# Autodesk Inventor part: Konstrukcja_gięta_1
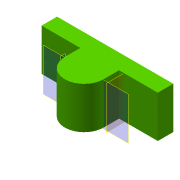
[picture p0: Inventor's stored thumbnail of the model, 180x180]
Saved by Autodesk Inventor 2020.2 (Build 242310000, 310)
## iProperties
Created: 2014-08
Part Number: Konstrukcja_gięta_1
Material: Ogólny
Document SubType Name: Modeling
Designer: F.Stasiak
Density: 1 g/cm^3
Appearance: Domyślna
Catalog Web Link: www.expertbooks.pl
Manager: www.cadconsulting.pl
Company: Fabian Stasiak CAD Consulting
Author: F.Stasiak
Subject: Zbiór ćwiczeń. Autodesk Inventor 2020. Kurs Professional
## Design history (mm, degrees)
sketch "Szkic1"
  geometry: L1 (-500, 200)-(-500, 0); L2 (-500, 0)-(0, 0); L3 (500, 0)-(500, -200); L4 (0, -200)-(0, 0); L5 (-500, 200)-(1000, 200); L6 (1000, 200)-(1000, 0); L7 (1000, 0)-(500, 0); A1 r 250 centre (250, -200) between (0, -200) and (500, -200); 1 further point
  constraints: 14 end point, 2 parallel, 2 perpendicular, 2 point on circle, 2 tangent, 1 centre point, 1 coincident, 1 collinear, 1 horizontal
  dimensions: "d18" = 1500 distance of L1.start L5.end; "d19" = 500 distance between parallel lines of L4 L1; "d20" = 250 radius of A1; "d21" = 200 distance of L1.start L1.end; "d22" = 200 distance of L3.start L3.end
extrude "Wyciągnięcie proste1" new body sketch "Szkic1" distance "d3" = 540; taper "d4" = 0 deg
hole "Otwór1" diameter "d7" = 12.7; stored, may be unused: countersink angle "d11" = 90 deg, drill point angle "d13" = 118 deg; dims "d5" = 150, "d6" = 50, "d8" = 6, "d9" = 4, "d10" = 2, "d12" = 100
node "Płaszczyzna konstrukcyjna1"
node "Płaszczyzna konstrukcyjna2"
node "Płaszczyzna konstrukcyjna3"
hole "Otwór2" diameter "d25" = 12.7; stored, may be unused: countersink angle "d29" = 90 deg, drill point angle "d31" = 118 deg; dims "d23" = 150, "d24" = 50, "d26" = 6, "d27" = 4, "d28" = 2, "d30" = 100
node "Bryła1"
